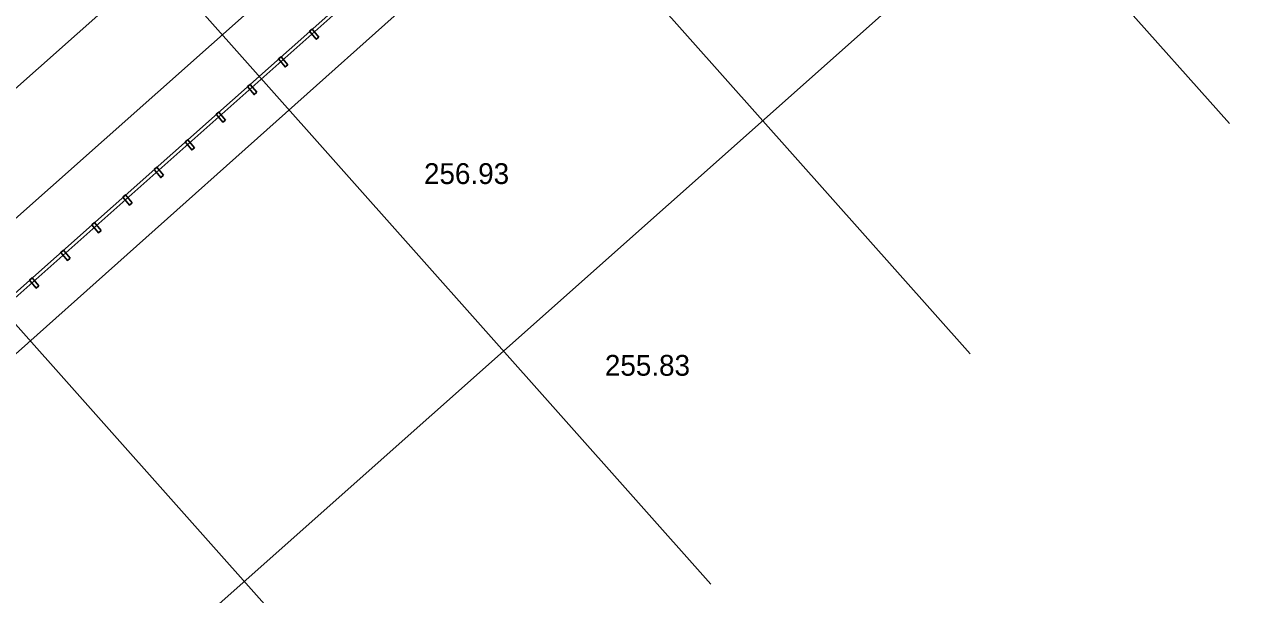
# Model space of a CAD drawing. Extents: x 49683 to 58852, y 49525 to 54803.
# Drawn here: x 53372.4 to 53548.7, y 51284.7 to 51366.9 of the extents above; entities that cross this region are included whole.
import ezdxf

# ---------------------------------------------------------------- set-up
doc = ezdxf.new("R2010")
doc.units = 0
for name, color, linetype in [('Level 11', 7, 'Continuous'), ('Level 19', 7, 'Continuous'), ('Level 20', 7, 'Continuous'), ('Level 27', 7, 'Continuous'), ('Level 29', 7, 'Continuous'), ('Level 32', 7, 'Continuous'), ('Level 33', 7, 'Continuous'), ('Level 50', 7, 'Continuous'), ('Level 63', 7, 'Continuous')]:
    doc.layers.add(name, color=color, linetype=linetype)

msp = doc.modelspace()

# ---------------------------------------------------------------- linework, layer by layer
at = {"layer": 'Level 11'}
msp.add_line((53245.86, 51207.55), (53944.24, 51830.77), dxfattribs=at)
at = {"layer": 'Level 19'}
msp.add_line((52714.15, 50773.62), (54181.77, 52078.16), dxfattribs=at)
at = {"layer": 'Level 20'}
msp.add_line((52723.45, 50763.15), (53495.78, 51449.66), dxfattribs=at)
at = {"layer": 'Level 27'}
for p, q in [((52953.7, 50957.11), (53467.54, 51413.86)), ((52954.03, 50956.74), (53467.88, 51413.49))]:
    msp.add_line(p, q, dxfattribs=at)
for points in [[(53414.88, 51365.04), (53414.5, 51364.72), (53413.54, 51365.87), (53413.92, 51366.19)], [(53410.4, 51361.05), (53410.01, 51360.73), (53409.05, 51361.88), (53409.44, 51362.2)], [(53405.91, 51357.07), (53405.53, 51356.74), (53404.57, 51357.9), (53404.95, 51358.22)], [(53401.43, 51353.08), (53401.05, 51352.76), (53400.08, 51353.91), (53400.47, 51354.23)], [(53396.95, 51349.09), (53396.56, 51348.77), (53395.6, 51349.92), (53395.98, 51350.24)], [(53392.46, 51345.11), (53392.08, 51344.79), (53391.12, 51345.94), (53391.5, 51346.26)], [(53387.98, 51341.12), (53387.59, 51340.8), (53386.63, 51341.95), (53387.01, 51342.27)], [(53383.49, 51337.13), (53383.11, 51336.81), (53382.15, 51337.97), (53382.53, 51338.29)], [(53379.01, 51333.15), (53378.62, 51332.83), (53377.66, 51333.98), (53378.05, 51334.3)], [(53374.52, 51329.16), (53374.14, 51328.84), (53373.18, 51329.99), (53373.56, 51330.31)]]:
    msp.add_lwpolyline(points, close=True, dxfattribs=at)
at = {"layer": 'Level 29'}
msp.add_line((52714.15, 50773.62), (54181.77, 52078.16), dxfattribs=at)
at = {"layer": 'Level 33'}
msp.add_line((52763.97, 50717.56), (53711.35, 51559.67), dxfattribs=at)
at = {"layer": 'Level 50'}
for p, q in [((53386.66, 51531.95), (53546.1, 51352.57)), ((53349.29, 51498.74), (53508.73, 51319.36)), ((53311.92, 51465.52), (53471.36, 51286.14)), ((53274.55, 51432.3), (53433.99, 51252.92))]:
    msp.add_line(p, q, dxfattribs=at)
at = {"layer": 'Level 63'}
for p, q in [((53460.4, 51436.95), (52726.11, 50784.25)), ((53460.4, 51436.95), (52800.86, 50850.69)), ((52810.16, 50840.23), (53469.7, 51426.49))]:
    msp.add_line(p, q, dxfattribs=at)

# ---------------------------------------------------------------- texts
at = {"layer": 'Level 32'}
for s, p in [('256.93', (53430.02, 51343.85)), ('255.83', (53456.09, 51316.21))]:
    msp.add_text(s, height=3, dxfattribs=at).set_placement(p)

doc.saveas('drawing.dxf')
